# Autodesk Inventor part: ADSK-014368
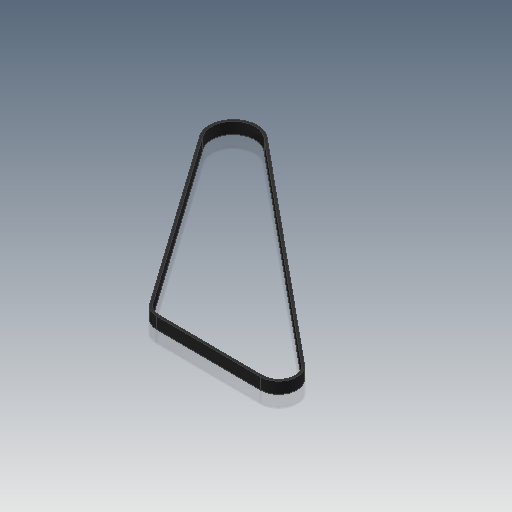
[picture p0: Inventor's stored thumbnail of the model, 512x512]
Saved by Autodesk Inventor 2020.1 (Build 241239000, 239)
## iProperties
Created: 2019-10
Part Number: ADSK-014368
Material: Gummi
Document SubType Name: Modeling
Designer: lutzd
Mass: 357.742 g
Surface Area: 1522.65 cm^2
Volume: 384.669 cm^3
Density: 0.93 g/cm^3
Appearance: Gummi - Schwarz
VLDS_Profile: Default Part
VLDS_TimeStamp: 2016-07-29
VLDS_FailCnt: 0
VLDS_AcceptCnt: 0
Dimensions: 604,5x32x731,5 mm
Mass: 0,358 kg
DocNumber: ADSK-014368
Folder: 01 - Themengebiete\Simplification\01 - Packaging machine\Parts\
VDS_Category: 3D Komponenten
VDS_NumSchm: Autodesk
VLT_Material: Gummi
Title: belt
Author: lutzd
Revision Number: -
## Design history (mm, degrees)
feature "Fläche1"
feature "Fläche2"
feature "Fläche3"
sketch "Skizze1"
  geometry: L1 (291.298, -44.999)-(-0.253, -43.294); L2 (-35.363, -24.977)-(-371.764, 451.308); L3 (-283.068, 533.511)-(320.236, 34.681); L4 (-376.665, 447.847)-(-40.264, -28.438); L5 (-0.288, -49.293)-(291.263, -50.999); L6 (324.06, 39.305)-(-279.245, 538.136); A1 r 61 centre (-321.939, 486.5) between (-371.764, 451.308) and (-283.068, 533.511) reference; A2 r 43.294 centre (0, 0) between (-0.253, -43.294) and (-35.363, -24.977) reference; A3 r 45 centre (291.561, 0) between (291.298, -44.999) and (320.236, 34.681) reference; A4 r 45 centre (291.561, 0) between (291.298, -44.999) and (320.236, 34.681); A5 r 43.294 centre (0, 0) between (-35.363, -24.977) and (-0.253, -43.294); A6 r 61 centre (-321.939, 486.5) between (-283.068, 533.511) and (-371.764, 451.308); A7 r 49.294 centre (0, 0) between (-40.264, -28.438) and (-0.288, -49.293); A8 r 51 centre (291.561, 0) between (291.263, -50.999) and (324.06, 39.305); A9 r 67 centre (-321.939, 486.5) between (-279.245, 538.136) and (-376.665, 447.847); 1 further point
  constraints: 18 point on circle, 12 end point, 7 tangent, 6 centre point, 3 concentric, 5 other
  dimensions: "d0" = 6 distance between parallel lines of L2 L4
extrude "Extrusion1" new body sketch "Skizze1" stored distance "d1" = 32; taper "d2" = 0 deg
node "Volumenkörper1"
node "Flä1"
node "Flä2"
node "Flä3"
